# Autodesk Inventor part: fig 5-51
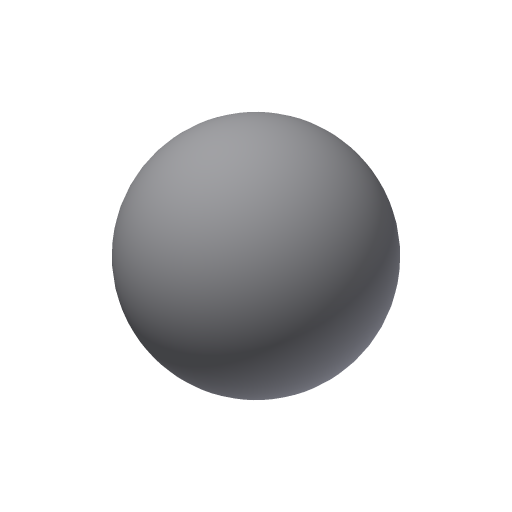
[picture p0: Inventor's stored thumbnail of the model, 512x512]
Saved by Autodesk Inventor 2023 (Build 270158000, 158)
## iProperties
Created: 2012-07
Part Number: fig 5-51
Material: Generic
Document SubType Name: Modeling
Designer: CADCIM
Density: 1 g/cm^3
Appearance: Default
Author: CADCIM
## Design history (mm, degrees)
sketch "Sketch1"
  geometry: L1 (7.807, -5.174)-(-7.807, 5.174); A1 r 9.366 centre (0, 0) between (7.807, -5.174) and (-7.807, 5.174)
  constraints: 2 end point, 2 point on circle, 1 centre point, 1 midpoint
revolve "Revolution1" sketch "Sketch1" stored, may be unused: angle "d0" = 90 deg
workpoint "Work Point1"
body "Solid1"
